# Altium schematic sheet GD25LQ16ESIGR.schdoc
size 127 x 101 mm
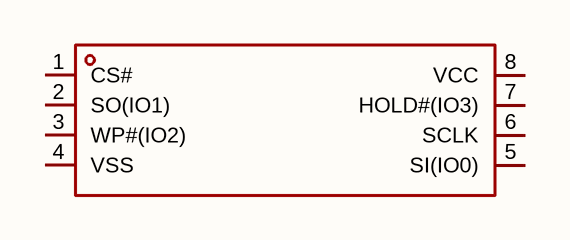
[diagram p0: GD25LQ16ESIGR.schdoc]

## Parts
U?  gd25lq16esigr  [SOIC-8_L5.3-W5.3-P1.27-LS8.0-BL]  (value not drawn)

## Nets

Not connected (* = marked no-connect by the designer): U? 1(CS#) 2(SO(IO1)) 3(WP#(IO2)) 4(VSS) 5(SI(IO0)) 6(SCLK) 7(HOLD#(IO3)) 8(VCC)

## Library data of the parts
U? = gd25lq16esigr: 接口类型:SPI;存储容量:16Mbit;时钟频率(fc):133MHz;; Manufacturer: GigaDevice(兆易创新); AddInBom: yes; ModelId: f83d990ad74f400caf5ac920b7771508; ModelName: SOIC-8_L5.3-W5.3-H1.9-LS7.9-P1.27; ModelTransform: 208.661,311.25654,0,0,0,0,-0.0005,0.0005,0; Interface: SPI; Memory Size: 16Mbit; Clock Frequency: 133MHz; Voltage - Supply: 1.65V~2.1V; Page Programming Time (Tpp): 2.5ms; Data Retention - TDR (Year): 20年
